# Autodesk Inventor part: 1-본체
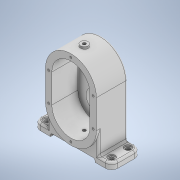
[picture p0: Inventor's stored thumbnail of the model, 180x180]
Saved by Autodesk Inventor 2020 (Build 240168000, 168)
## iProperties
Created: 2021-05
Part Number: 1-본체
Material: 일반
Document SubType Name: Modeling
Designer: Owner
Density: 1 g/cm^3
Appearance: 기본값
Author: Owner
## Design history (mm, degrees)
sketch "스케치2"
  geometry: L1 (0, 0)-(0, -45); L2 (-40, 0)-(-40, -45); L3 (40, -45)-(40, 0); A1 r 40 centre (0, 0) between (40, 0) and (-40, 0); A2 r 40 centre (0, -45) between (-40, -45) and (40, -45); 2 further points
  constraints: 8 end point, 4 point on circle, 4 tangent, 2 centre point, 1 coincident, 1 midpoint, 1 parallel, 1 vertical
  dimensions: "d12" = 45 distance of L1.start L1.end; "d13" = 80 distance between parallel lines of L3 L2
extrude "돌출3" new body sketch "스케치2" distance "d14" = 21; taper "d16" = 0 deg; dims "d15" = 28, "d17" = 0
sketch "스케치6"
  geometry: L1 (0, 0)-(0, -45); L2 (-30, 0)-(-30, -45); L3 (30, -45)-(30, 0); A1 r 30 centre (0, 0) between (30, 0) and (-30, 0); A2 r 30 centre (0, -45) between (-30, -45) and (30, -45); A3 r 40 centre (0, -45) between (-40, -45) and (40, -45) reference; 1 further point
  constraints: 8 end point, 4 point on circle, 4 tangent, 2 centre point, 1 coincident, 1 midpoint, 1 parallel, 1 vertical
  dimensions: "d18" = 30 radius of A1
extrude "돌출4" cut sketch "스케치6" distance "d19" = 41; taper "d20" = 0 deg
node "작업 평면4"
sketch "스케치8"
  geometry: L1 (-61, -28)-(61, -28); L2 (61, -28)-(61, 18); L3 (61, 18)-(-61, 18); L4 (-61, 18)-(-61, -28); L5 (-61, -28)-(61, 18); L6 (61, -28)-(-61, 18); L7 (-40, -28)-(40, -28) reference; L8 (0, 0)-(0, -58.176); 1 further point
  constraints: 14 end point, 2 midpoint, 2 parallel, 1 collinear, 1 horizontal, 1 perpendicular, 1 vertical, 1 other
  dimensions: "d26" = 122 distance of L1.start L1.end; "d27" = 46 distance of L1.end L2.end
extrude "돌출6" join sketch "스케치8" distance "d28" = 10; taper "d29" = 0 deg
sketch "스케치9"
  geometry: L1 (21, 47)-(21, 10); L2 (0, 10)-(45.801, 10) reference; L3 (61, 102.696)-(61, -8.083); L4 (101, 47)-(101, 10); L5 (76.199, 10)-(122, 10) reference; A1 r 40 centre (61, 47) between (21, 47) and (101, 47) reference; 1 further point
  constraints: 6 end point, 2 point on line, 2 symmetric about line, 2 vertical, 1 coincident
extrude "돌출7" join sketch "스케치9" distance "d30" = 46; taper "d31" = 0 deg
extrude "돌출8" join sketch "스케치9" distance "d32" = 46; taper "d33" = 0 deg
node "작업 평면5"
sketch "스케치10"
  geometry: C1 r 6 at (0, 0); 1 further point
  constraints: 1 centre point, 1 coincident
  dimensions: "d36" = 12 diameter of C1
extrude "돌출9" join sketch "스케치10" stored distance "d37" = 46; taper "d38" = 0 deg
sketch "스케치11"
  geometry: C1 r 6 at (0, 0) reference; 2 further points
  constraints: 1 coincident
hole "구멍1" sketch "스케치11" at (0, 0) diameter "d39" = 4.917; stored, may be unused: countersink angle "d43" = 90 deg, drill point angle "d45" = 0 deg; dims "d40" = 12, "d41" = 12.6, "d42" = 2, "d44" = 17.1
fillet "모깎기1" dims "d46" = 10
sketch "스케치13"
  geometry: A1 r 10 centre (-51, 18) between (-51, 28) and (-61, 18) reference; A2 r 10 centre (51, 18) between (61, 18) and (51, 28) reference; A3 r 10 centre (51, -8) between (51, -18) and (61, -8) reference; A4 r 10 centre (-51, -8) between (-61, -8) and (-51, -18) reference; 1 further point
hole "구멍2" sketch "스케치13" at (-51, 18), (-51, -8), (51, -8), (51, 18) diameter "d47" = 6.6; stored, may be unused: countersink angle "d51" = 90 deg, drill point angle "d53" = 0 deg; dims "d48" = 12, "d49" = 11, "d50" = 2, "d52" = 17.1
sketch "스케치14"
  geometry: L1 (51, -28)-(-51, -28) reference; L2 (-51, 18)-(51, 18) reference; L3 (0, -51.959)-(0, 89.002); L4 (35, -28)-(35, 18); L5 (-35, -28)-(-35, 18); 1 further point
  constraints: 6 end point, 5 point on line, 3 vertical, 1 other
  dimensions: "d54" = 70 distance between parallel lines of L5 L4
extrude "돌출10" cut sketch "스케치14" distance "d55" = 5; taper "d56" = 0 deg
sketch "스케치15"
  geometry: L1 (0, 0)-(0, -45); L2 (-26, 0)-(-26, -45); L3 (26, -45)-(26, 0); A1 r 26 centre (0, 0) between (26, 0) and (-26, 0); A2 r 26 centre (0, -45) between (-26, -45) and (26, -45); 2 further points
  constraints: 8 end point, 4 point on circle, 4 tangent, 2 centre point, 1 coincident, 1 midpoint, 1 parallel, 1 vertical
  dimensions: "d57" = 52 distance between parallel lines of L3 L2; "d58" = 45 distance of L1.start L1.end
extrude "돌출11" join sketch "스케치15" distance "d59" = 11; taper "d60" = 0 deg
sketch "스케치16"
  geometry: L1 (-26, 0)-(-26, -45) reference; L2 (26, -45)-(26, 0) reference; L3 (-26, -45)-(-26, 0) reference; L4 (-26, -30)-(26, -30); A1 r 26 centre (0, 0) between (26, 0) and (-26, 0) reference; 2 further points
  constraints: 2 end point, 2 point on line, 1 perpendicular
  dimensions: "d61" = 30 distance from line of L4 point (0, 0)
extrude "돌출12" cut sketch "스케치16" distance "d62" = 3; taper "d63" = 0 deg
sketch "스케치17" dims "d64" = 40
  geometry: 3 further points
  constraints: 2 vertical alignment, 1 coincident, 2 other
hole "구멍3" sketch "스케치17" at (0, 20) diameter "d65" = 3.242; stored, may be unused: countersink angle "d69" = 90 deg, drill point angle "d71" = 118 deg; dims "d66" = 8, "d67" = 12.24, "d68" = 3.58, "d70" = 10
sketch "스케치18"
  geometry: L1 (0, 0)-(0, -48.739); L2 (0, -20)-(30, -20) reference; L3 (14, -20)-(14, -28); L4 (14, -28)-(11, -28); L5 (11, -28)-(11, -32); L6 (11, -32)-(14, -32); L7 (14, -32)-(14, -36); L8 (26, -36)-(0, -36) reference; L9 (14, -20)-(0, -20); L10 (0, -28)-(0, -36) reference; L11 (14, -36)-(0, -36)
  constraints: 16 end point, 7 perpendicular, 2 point on line, 1 collinear, 1 vertical
  dimensions: "d75" = 28 diameter of L3 L1; "d76" = 22 diameter of L5 L1; "d77" = 8 distance of L3.start L3.end; "d78" = 4 distance of L6.end L7.end
revolve "회전2" sketch "스케치18" stored, may be unused: angle "d80" = 90 deg
sketch "스케치19"
  geometry: L1 (-45, 21)-(-45, -20) reference; L2 (-45, -20)-(0, -20) reference; L3 (-45, -20)-(-45, -47.398); L4 (-31, -20)-(-31, -28); L5 (-31, -28)-(-35, -28); L6 (-35, -28)-(-35, -32); L7 (-35, -32)-(-45, -32); 1 further point
  constraints: 10 end point, 3 perpendicular, 2 point on line, 2 vertical
  dimensions: "d81" = 8 distance of L4.start L4.end; "d82" = 28 diameter of L4 L3; "d83" = 20 diameter of L6 L3; "d84" = 4 distance of L5.end L6.end
revolve "회전3" sketch "스케치19" stored, may be unused: angle "d85" = 90 deg
sketch "스케치20"
  geometry: L1 (40, 21)-(-40, 21) reference; 2 further points
  constraints: 1 coincident
  dimensions: "d86" = 21 distance from line of point (0, 0) L1
hole "구멍4" sketch "스케치20" at (0, 0) diameter "d87" = 4.917; stored, may be unused: countersink angle "d91" = 90 deg, drill point angle "d93" = 0 deg; dims "d88" = 12, "d89" = 12, "d90" = 1, "d92" = 17.1
sketch "스케치21"
  geometry: L1 (0, 0)-(0, -101.673); L2 (-87.317, -80)-(87.317, -80); L3 (-51, -92)-(-35, -92) reference
  constraints: 4 end point, 2 horizontal, 1 symmetric about line, 1 vertical
  dimensions: "d94" = 12 distance between parallel lines of L3 L2
feature "엠보싱1" sketch "스케치21" dims "d12" = 45, "d13" = 80, "d95" = 0.5, "d96" = 0
fillet "모깎기2" dims "d97" = 3
sketch "스케치22"
  geometry: L1 (0, 0)-(0, -45); L2 (-35, 0)-(-35, -45); L3 (35, -45)-(35, 0); L4 (-52.867, -22.5)-(54.021, -22.5); A1 r 35 centre (0, 0) between (35, 0) and (-35, 0); A2 r 35 centre (0, -45) between (-35, -45) and (35, -45); 8 further points
  constraints: 10 end point, 5 point on circle, 4 tangent, 3 coincident, 3 symmetric about line, 2 centre point, 1 horizontal, 1 midpoint, 1 parallel, 1 point on line, 1 vertical, 1 vertical alignment
  dimensions: "d98" = 35 radius of A1; "d99" = 45 distance of L1.start L1.end
hole "구멍5" sketch "스케치22" at (0, 35), (-35, 0), (35, 0), (0, -80), (-35, -45), (35, -45) diameter "d100" = 3.242; stored, may be unused: countersink angle "d104" = 90 deg, drill point angle "d106" = 118 deg; dims "d101" = 8, "d102" = 12, "d103" = 1, "d105" = 10
chamfer "모따기1" distance "d107" = 3; stored, may be unused: second distance "d108" = 2, angle "d109" = 45 deg
fillet "모깎기3" dims "d110" = 0.3
chamfer "모따기2" distance "d111" = 1; stored, may be unused: second distance "d112" = 2, angle "d113" = 45 deg
fillet "모깎기4" dims "d114" = 3
fillet "모깎기5" dims "d115" = 3
fillet "모깎기6" dims "d116" = 3
fillet "모깎기7" dims "d117" = 3
fillet "모깎기8" dims "d118" = 3
node "솔리드2"
pattern_circular "원형 패턴1" dims angle "d73" = 360 deg
feature "A9D066F2-1C7D-4E18-AEED-F7BC21143FA4" dims "d47" = 6.6, "d48" = 12, "d49" = 11, "d50" = 2, "d51" = 90 deg, "d52" = 17.1, "d53" = 0
other parameters: "d21" = -92, "d34" = -135
